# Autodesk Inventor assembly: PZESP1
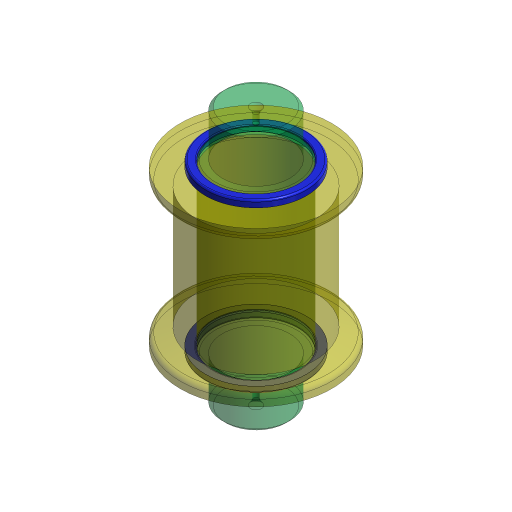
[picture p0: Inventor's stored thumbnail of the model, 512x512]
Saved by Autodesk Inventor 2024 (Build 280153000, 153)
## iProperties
Company: ATC
Shininess: 20.0
Length Units: 11269
Angle Units: 11279
Time Units: 11290
Mass Units: 11283
Length Display Precision: 3
Angle Display Precision: 2
Compacted: True
Created: 2023-03
Part Number: PZESP1
Document SubType Name: Assembly
Designer: Andrzej Jaskulski
Mass: 60.2464 g
Surface Area: 198.901 cm^2
Volume: 60.2464 cm^3
Density: 1 g/cm^3
Checked By: A.J.
Engr Approved By: Andrzej Jaskulski
Mfg Approved By: Andrzej Jaskulski
Authority: A.J.
Density: 0.0
Volumn: 0.0
Area: 0.0
PropertySet Name: Model Information
Control State: 0
Master: False
Checked Out: False
Title: A.J.: Kurs R2024-MEP
Author: Andrzej Jaskulski
Revision Number: 1/24
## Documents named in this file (4)
- C:\Users\AndJas\Documents\R2024-MEP\Obszar roboczy\PZESP1.iam
- C:\Users\AndJas\Documents\R2024-MEP\Obszar roboczy\Wałek.ipt
- C:\Users\AndJas\Documents\R2024-MEP\Obszar roboczy\Podkładka.ipt
- C:\Users\AndJas\Documents\R2024-MEP\Obszar roboczy\Rolka.ipt
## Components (4 placed, 3 different names)
1. Wałek:1 — Wstawiające:3
2. Podkładka:1 — Wstawiające:2, Wstawiające:3
3. Podkładka:2 — Wstawiające:1
4. Rolka:1 — Wstawiające:1, Wstawiające:2
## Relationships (3: Insert 3)
- Wstawiające:1 [Insert]: Podkładka:2 ↔ Rolka:1
- Wstawiające:2 [Insert]: Podkładka:1 ↔ Rolka:1
- Wstawiające:3 [Insert]: Wałek:1 ↔ Podkładka:1
